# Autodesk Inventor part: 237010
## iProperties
Created: 2006-08
Part Number: 237010
Material: FSt vz
Description: Federring
Vendor: Autodesk Inc.
Document SubType Name: Modeling
Standard: DIN 127
Designer: I.Baliuc
Standards Organization: DIN
Language: de-DE
Size Designation: A 6
Categories: <MemberInstance Version="R10.0.0"><Categories><Category DisplayName="Schrauben" InternalName="e4da775c-781d-43d5-af7c-5136215cf5a6" Mnemonic="FSTN"><Category Di
Density: 7.85 g/cm^3
Mass: 0.935288 g
Surface Area: 2.48728 cm^2
Volume: 0.119145 cm^3
Abmessung: A 6
Author: T.Messerschmitt
Comments: DIN 127 - A 6
Revision Number: 237010
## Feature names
1. Körper [Extrusion]
2. Schnitt [Extrusion]
